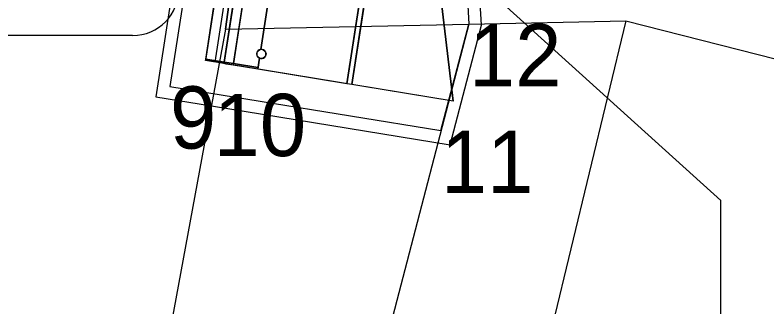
# Model space of a CAD drawing. Extents: x -728800 to -728100, y -1073200 to -1072700.
# Drawn here: x -728506.62 to -728494.54, y -1073056.8 to -1073052.11 of the extents above; entities that cross this region are included whole.
import ezdxf

# ---------------------------------------------------------------- set-up
doc = ezdxf.new("R2010")
doc.units = 0
for name, color, linetype in [('_NOR-návrh tenká', 7, 'Continuous'), ('_NOR-VDZ', 7, 'Continuous'), ('_NOR-šraf_+6', 7, 'Continuous'), ('_NOR-šraf_bezbariéra', 7, 'Continuous'), ('_NOR-šraf_chodník', 7, 'Continuous'), ('_NOR-šraf_varovný pás', 7, 'Continuous'), ('_NOR-šraf_vozovka', 7, 'Continuous'), ('_NOR-šraf_zeleň', 7, 'Continuous'), ('A1_OBVOD Spravy železnic', 7, 'Continuous'), ('A2_OBVOD STAVBY', 7, 'Continuous'), ('B1_body_poloha', 7, 'Continuous'), ('B2_body_číslo', 7, 'Continuous'), ('K_01_Hranice parcel', 7, 'Continuous'), ('KTA_členění PS a SO', 7, 'Continuous'), ('ZA_02_Dočasný_do_1_roku', 7, 'Continuous')]:
    doc.layers.add(name, color=color, linetype=linetype)

msp = doc.modelspace()

# ---------------------------------------------------------------- linework, layer by layer
at = {"layer": '_NOR-návrh tenká'}
for p, q in [((-728499.581, -1073053.497), (-728499.904, -1073050.807)), ((-728503.263, -1073052.895), (-728503.559, -1073052.847)), ((-728499.581, -1073053.497), (-728503.263, -1073052.895))]:
    msp.add_line(p, q, dxfattribs=at)
for points in [[(-728502.819, -1073048.076), (-728503.559, -1073052.847)], [(-728502.523, -1073048.119), (-728503.263, -1073052.895)], [(-728502.374, -1073048.141), (-728503.115, -1073052.92)], [(-728500.544, -1073048.409), (-728501.289, -1073053.218)], [(-728500.465, -1073048.422), (-728501.21, -1073053.23)], [(-728502.31, -1073050.336), (-728502.671, -1073052.666)], [(-728502.693, -1073052.808), (-728502.721, -1073052.984)]]:
    msp.add_lwpolyline(points, dxfattribs=at)
msp.add_circle((-728502.662, -1073052.74), 0.075, dxfattribs=at)
at = {"layer": '_NOR-VDZ'}
msp.add_lwpolyline([(-728502.671, -1073048.097), (-728503.411, -1073052.871)], dxfattribs=at)
at = {"layer": '_NOR-šraf_+6'}
for p, q in [((-728500.465, -1073048.422), (-728501.21, -1073053.231)), ((-728501.289, -1073053.218), (-728500.958, -1073051.084)), ((-728501.21, -1073053.231), (-728501.289, -1073053.218))]:
    msp.add_line(p, q, dxfattribs=at)
at = {"layer": '_NOR-šraf_bezbariéra'}
for p, q in [((-728503.259, -1073052.871), (-728502.523, -1073048.119)), ((-728502.374, -1073048.141), (-728503.111, -1073052.894)), ((-728503.111, -1073052.894), (-728503.259, -1073052.871)), ((-728503.259, -1073052.871), (-728503.111, -1073052.894))]:
    msp.add_line(p, q, dxfattribs=at)
msp.add_lwpolyline([(-728503.111, -1073052.894), (-728503.115, -1073052.92), (-728503.229, -1073052.901), (-728503.263, -1073052.895), (-728503.259, -1073052.871)], dxfattribs=at)
at = {"layer": '_NOR-šraf_chodník'}
for p, q in [((-728502.671, -1073052.666), (-728502.31, -1073050.336)), ((-728500.994, -1073051.315), (-728501.289, -1073053.218)), ((-728502.721, -1073052.984), (-728502.693, -1073052.808)), ((-728501.289, -1073053.218), (-728502.721, -1073052.984))]:
    msp.add_line(p, q, dxfattribs=at)
msp.add_arc((-728502.662, -1073052.74), 0.075, 245.3796, 96.9883, dxfattribs=at)
at = {"layer": '_NOR-šraf_varovný pás'}
msp.add_line((-728502.31, -1073050.336), (-728502.671, -1073052.666), dxfattribs=at)
for points in [[(-728502.693, -1073052.808), (-728502.716, -1073052.955), (-728503.111, -1073052.894), (-728502.409, -1073048.363)], [(-728503.115, -1073052.92), (-728503.111, -1073052.894), (-728502.716, -1073052.955), (-728502.721, -1073052.984), (-728503.115, -1073052.92)]]:
    msp.add_lwpolyline(points, dxfattribs=at)
msp.add_arc((-728502.662, -1073052.74), 0.075, 96.9883, 245.3796, dxfattribs=at)
at = {"layer": '_NOR-šraf_vozovka'}
for p, q in [((-728503.556, -1073052.825), (-728502.819, -1073048.076)), ((-728503.106, -1073051.882), (-728503.259, -1073052.871)), ((-728503.259, -1073052.871), (-728503.556, -1073052.825))]:
    msp.add_line(p, q, dxfattribs=at)
msp.add_lwpolyline([(-728503.556, -1073052.825), (-728503.259, -1073052.871), (-728503.263, -1073052.895), (-728503.559, -1073052.847), (-728503.556, -1073052.825)], dxfattribs=at)
at = {"layer": '_NOR-šraf_zeleň'}
for p, q in [((-728501.21, -1073053.231), (-728500.465, -1073048.422)), ((-728499.904, -1073050.807), (-728499.581, -1073053.497)), ((-728499.581, -1073053.497), (-728501.21, -1073053.231))]:
    msp.add_line(p, q, dxfattribs=at)
at = {"layer": 'A1_OBVOD Spravy železnic'}
for points in [[(-728503.24, -1073052.34), (-728501.19, -1073037.94), (-728499.78, -1073032.61), (-728497.54, -1073030.15), (-728493.68, -1073027.94), (-728443.97, -1073014.59), (-728443.68, -1073014.51), (-728441.09, -1073023.23), (-728428.92, -1073019.94), (-728429.82, -1073016.43), (-728427.49, -1073015.84), (-728421.24, -1073014.23), (-728422.34, -1073010.27), (-728422.77, -1073008.34), (-728418.21, -1073007), (-728380.57, -1072997.2), (-728343.1, -1072987.57), (-728330.49, -1072984.52), (-728326.79, -1072988.95)], [(-728503.24, -1073052.34), (-728499.33, -1073052.26), (-728496.81, -1073052.21), (-728491.97, -1073053.44), (-728470.97, -1073054.08), (-728434.43, -1073049.27), (-728361.73, -1073039.5), (-728349.166, -1073038.984)]]:
    msp.add_lwpolyline(points, dxfattribs=at)
at = {"layer": 'A2_OBVOD STAVBY'}
msp.add_lwpolyline([(-728503.756, -1073049.547), (-728504.358, -1073053.426), (-728503.463, -1073053.572), (-728499.628, -1073054.199), (-728499.129, -1073052.28), (-728499.2, -1073051.021), (-728494.25, -1073049.503), (-728493.918, -1073046.515)], dxfattribs=at)
at = {"layer": 'B1_body_poloha'}
for p, q in [((-728499.33, -1073052.26), (-728499.33, -1073052.26)), ((-728504.13, -1073053.26), (-728504.13, -1073053.26)), ((-728503.43, -1073053.38), (-728503.43, -1073053.38)), ((-728499.78, -1073053.97), (-728499.78, -1073053.97))]:
    msp.add_line(p, q, dxfattribs=at)
at = {"layer": 'K_01_Hranice parcel'}
for p, q in [((-728502.6, -1073047.92), (-728503.24, -1073052.34)), ((-728499.33, -1073052.26), (-728504.87, -1073073.55)), ((-728503.24, -1073052.34), (-728499.33, -1073052.26)), ((-728499.33, -1073052.26), (-728496.81, -1073052.21)), ((-728496.81, -1073052.21), (-728498.42, -1073058.87))]:
    msp.add_line(p, q, dxfattribs=at)
for points in [[(-728496.81, -1073052.21), (-728491.97, -1073053.44), (-728477.97, -1073053.19)], [(-728503.24, -1073052.34), (-728506.32, -1073069.08), (-728508.676, -1073080.788), (-728509.816, -1073090.065)]]:
    msp.add_lwpolyline(points, dxfattribs=at)
at = {"layer": 'KTA_členění PS a SO'}
for p, q in [((-728495.283, -1073055.094), (-728501.186, -1073049.755)), ((-728495.283, -1073057.094), (-728495.283, -1073055.094))]:
    msp.add_line(p, q, dxfattribs=at)
msp.add_lwpolyline([(-728504.729, -1073052.444), (-728509.729, -1073052.444)], dxfattribs=at)
msp.add_arc((-728504.735, -1073051.694), 0.75, 270.4529, 89.5471, dxfattribs=at)
at = {"layer": 'ZA_02_Dočasný_do_1_roku'}
for points in [[(-728502.83, -1073049.48), (-728502.042, -1073043.972), (-728498.502, -1073044.372), (-728498.756, -1073046.192), (-728494.117, -1073046.49), (-728494.434, -1073049.35), (-728499.408, -1073050.876), (-728499.33, -1073052.26)], [(-728502.83, -1073049.48), (-728503.528, -1073049.379), (-728504.13, -1073053.261), (-728499.78, -1073053.97), (-728499.33, -1073052.26)]]:
    msp.add_lwpolyline(points, dxfattribs=at)

# ---------------------------------------------------------------- texts
at = {"layer": 'B2_body_číslo'}
for s, p in [('12', (-728499.33, -1073053.26)), ('9', (-728504.13, -1073054.26)), ('10', (-728503.43, -1073054.38)), ('11', (-728499.78, -1073054.97))]:
    msp.add_text(s, height=1, dxfattribs=at).set_placement(p)

doc.saveas('drawing.dxf')
